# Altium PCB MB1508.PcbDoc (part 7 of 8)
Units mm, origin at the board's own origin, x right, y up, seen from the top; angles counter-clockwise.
Board outline 129 x 77 mm, 4 copper layers (Top Layer, GND, POWER, Bottom Layer), stack 1.582 mm thick; 399 components, 297 nets, 1407 pads, 1316 vias.
Unrouted connection lines stored in the file: 535.
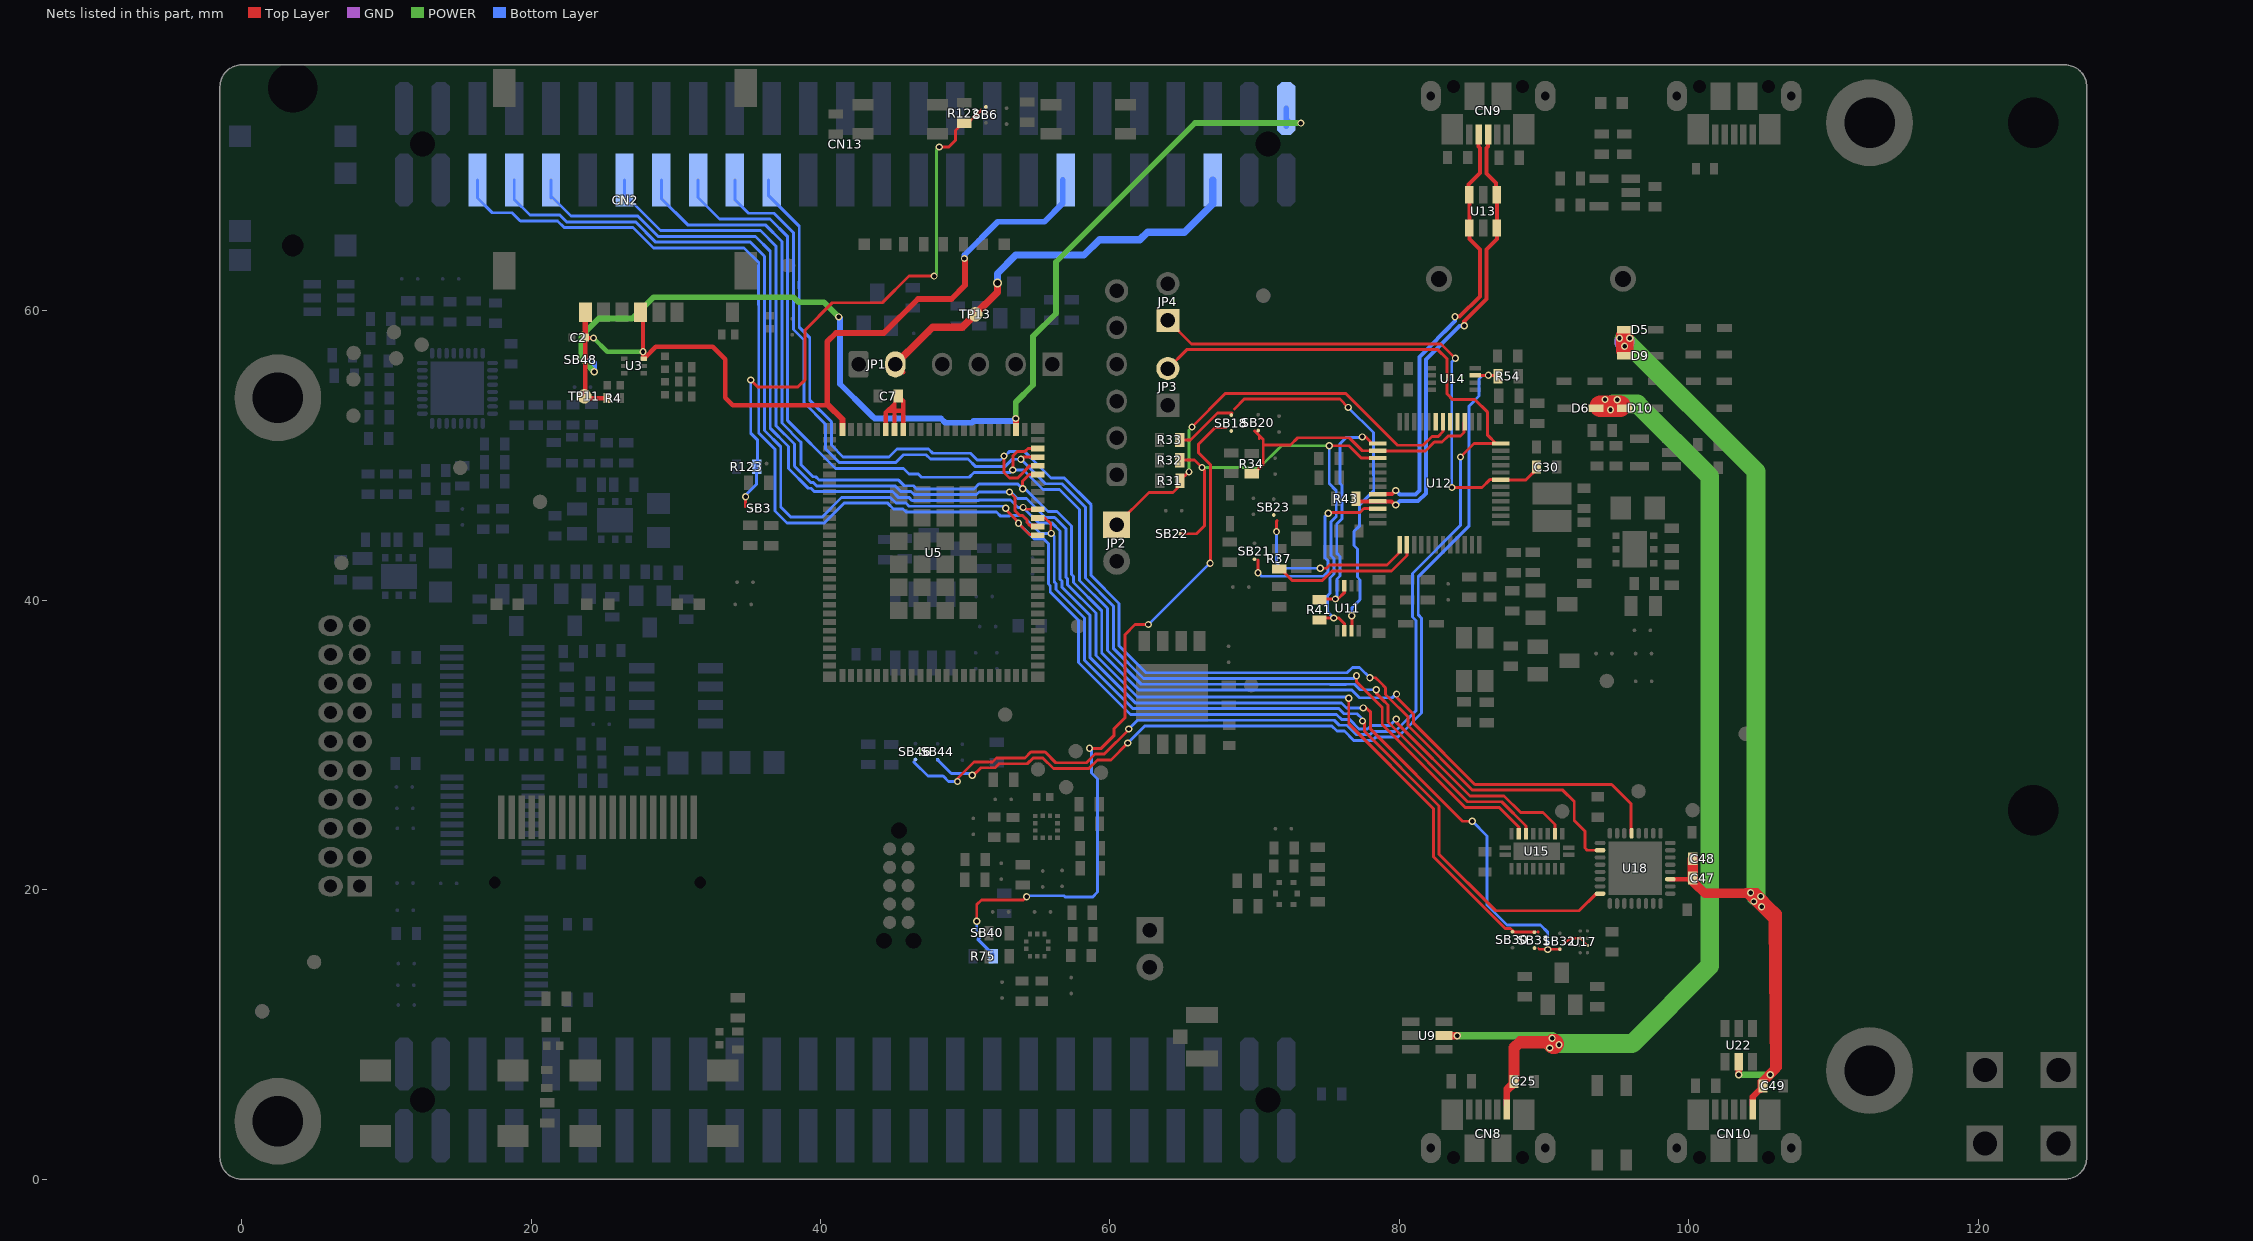
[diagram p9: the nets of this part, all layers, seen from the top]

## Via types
v1: diameter 0.5, hole 0.3, Top Layer to Bottom Layer, tented both sides, 1301 vias
v2: diameter 0.65, hole 0.4, Top Layer to Bottom Layer, tented both sides, 14 vias
v3: diameter 0.5/0.5/0.5/0.5 (per signal layer), hole 0.3, Top Layer to Bottom Layer, tented both sides, 1 vias

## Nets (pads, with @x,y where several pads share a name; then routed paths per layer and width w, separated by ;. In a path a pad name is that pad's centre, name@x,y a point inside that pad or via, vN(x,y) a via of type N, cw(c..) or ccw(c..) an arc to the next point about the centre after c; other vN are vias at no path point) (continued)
RFT_UART1_CTS: CN13.33 U5.26 U15.17 | length 93.1
  Top Layer w0.2: v1(53.29,49.011) 53.29,49.967 53.621,50.298 54.144,50.298 54.34,50.494 U5.26@55.013,50.494 ; v1(78.406,33.819) 78.406,33.572 78.854,33.124 79.218,32.76 79.218,31.582 84.719,26.081 87.073,26.081 88.756,24.398 U15.17@88.756,23.858
  Bottom Layer w0.2: CN13.33@31.54,69.045 31.54,67.84 33.031,66.349 36.508,66.349 37.731,65.125 37.731,62.35 37.728,62.347 37.728,61.229 37.731,61.226 37.731,52.413 41.031,49.113 45.73,49.113 46.124,48.719 46.759,48.719 46.975,48.503 50.275,48.503 50.608,48.837 53.116,48.837 v1(53.29,49.011) 54.02,49.011 55.375,47.656 56.515,47.656 57.904,46.267 57.904,41.379 59.835,39.447 59.835,36.524 62.161,34.198 75.204,34.198 75.206,34.197 76.324,34.197 76.325,34.198 76.902,34.198 77.281,33.819 v1(78.406,33.819)
RFT_UART1_RTS: CN13.35 U5.23 U18.29 | length 102.7
  Top Layer w0.2: v1(53.97,47.703) 53.97,48.237 54.426,48.694 U5.23@55.013,48.694 ; v1@79.823,33.579 79.823,33.287 80.99,32.12 80.99,31.507 85.216,27.281 94.674,27.281 95.997,25.958 95.997,23.954 U18.29@96.047,23.904
  Bottom Layer w0.2: CN13.35@29,69.045 29,67.774 30.825,65.949 36.187,65.949 37.331,64.805 37.331,62.516 37.328,62.513 37.328,61.063 37.331,61.06 37.331,52.245 38.661,50.915 ; 38.642,50.937 38.661,50.918 38.661,50.915 ; v1@79.823,33.579 79.513,33.269 77.245,33.269 76.716,33.798 76.491,33.798 76.49,33.797 75.04,33.797 75.039,33.798 61.996,33.798 59.435,36.358 59.435,39.282 57.479,41.238 57.479,41.657 57.352,41.784 57.352,45.126 56.347,46.131 55.723,46.131 54.151,47.703 v1(53.97,47.703) 53.636,48.037 50.939,48.037 50.606,47.703 46.643,47.703 46.428,47.919 45.793,47.919 45.444,48.267 45.398,48.313 39.895,48.313 39.667,48.541 39.49,48.541 38.661,49.37 38.661,50.915
  other v1: 79.812,33.519
RFT_UART1_RX: CN13.31 U5.25 U15.18 | length 88.8
  Top Layer w0.2: v1@53.981,49.894 U5.25@55.013,49.894 ; v1(77.043,34.789) 77.043,34.37 77.898,33.515 78.454,32.959 78.818,32.595 78.818,31.416 84.553,25.681 86.908,25.681 88.256,24.332 U15.18@88.256,23.858
  Bottom Layer w0.2: CN13.31@34.08,69.045 34.08,67.692 35.023,66.749 36.788,66.749 38.131,65.406 38.131,62.184 38.128,62.181 38.128,61.394 38.131,61.391 38.131,58.706 38.855,57.981 38.855,53.667 40.353,52.169 40.353,50.476 41.315,49.513 45.186,49.513 45.735,50.062 47.298,50.062 47.594,49.766 50.198,49.766 50.727,49.237 52.738,49.237 53.249,49.748 v1(53.849,49.748) ; v1@53.974,49.623 55.541,48.056 56.681,48.056 58.304,46.433 58.304,41.544 60.235,39.613 60.235,36.69 62.327,34.598 75.37,34.598 75.371,34.597 76.158,34.597 76.16,34.598 76.848,34.598 77.039,34.789 v1(77.043,34.789)
RFT_UART1_TX: CN13.29 U5.24 U18.2 | length 96.8
  Top Layer w0.2: v1(52.68,49.976) 52.68,48.843 53.062,48.461 53.628,48.461 54.461,49.294 U5.24@55.013,49.294 ; v1@52.74,49.951 52.74,49.963 v1@52.81,50.033 ; v1(77.964,34.65) 78.36,34.65 78.655,34.355 78.655,34.349 79.05,33.954 79.05,33.494 79.254,33.29 80.59,31.954 80.59,31.341 85.051,26.881 91.298,26.881 92.086,26.093 92.086,24.779 92.821,24.044 92.821,22.894 92.986,22.729 U18.2@93.872,22.729
  Bottom Layer w0.2: CN13.29@36.42,69.045 36.42,67.96 38.531,65.849 38.531,62.018 38.528,62.016 38.528,61.56 38.531,61.557 38.531,58.871 39.255,58.147 39.255,53.832 40.753,52.335 40.753,50.725 41.565,49.913 44.728,49.913 45.278,50.462 47.464,50.462 47.76,50.166 50.364,50.166 50.832,49.697 52.441,49.697 52.68,49.937 v1(52.68,49.976) ; v1@52.694,50.033 52.81,50.033 53.075,50.298 54.086,50.298 55.109,49.275 55.928,48.456 56.846,48.456 58.704,46.598 58.704,41.71 60.635,39.779 60.635,36.855 62.493,34.998 75.536,34.998 75.537,34.997 75.993,34.997 75.994,34.998 76.39,34.998 76.756,35.364 77.25,35.364 v1(77.964,34.65)
RFT_UART2_CTS: CN13.43 U5.16 U15.13 | length 108.1
  Top Layer w0.2: v1@52.884,46.369 52.884,46.194 v1@53.642,45.436 ; v1(53.685,45.32) 54.453,44.552 54.955,44.552 U5.16@55.013,44.494 ; v1(79.786,31.792) 79.786,31.579 84.885,26.481 87.239,26.481 88.384,25.335 89.919,25.335 90.756,24.498 U15.13@90.756,23.858
  Bottom Layer w0.2: CN13.43@18.84,69.045 18.84,67.703 19.917,66.626 21.981,66.626 22.452,66.155 27.211,66.155 28.617,64.749 35.155,64.749 36.131,63.772 36.131,63.013 36.128,63.01 36.128,60.566 36.131,60.563 36.131,51.73 37.255,50.607 37.255,46.457 37.966,45.746 40.095,45.746 41.461,47.113 44.814,47.113 45.208,46.719 45.901,46.719 46.116,46.503 52.621,46.503 v1@52.622,46.502 ; v1(53.685,45.32) 54.781,44.224 55.436,44.224 55.752,43.907 55.752,41.121 55.879,40.994 55.879,40.575 57.835,38.619 57.835,35.696 61.413,32.118 68.033,32.118 68.038,32.113 75.667,32.113 76.015,31.765 76.572,31.765 77.222,31.115 77.804,31.115 78.033,31.344 79.338,31.344 v1(79.786,31.792)
  other v1: 52.805,46.366
RFT_UART2_RTS: CN13.45 U5.18 U18.8 | length 118.3
  Top Layer w0.2: U5.18@55.013,45.694 55.516,45.694 55.911,45.299 55.911,44.658 v1(55.945,44.624) ; v1(77.45,31.665) 77.577,31.665 77.583,31.659 77.583,30.954 82.749,25.788 82.749,22.456 86.66,18.546 92.424,18.546 93.607,19.729 U18.8@93.872,19.729 U18.8@93.86,19.717
  Bottom Layer w0.2: CN13.45@16.3,69.045 16.3,67.794 17.312,66.782 18.679,66.782 19.256,66.205 21.836,66.205 ; 21.815,66.226 21.836,66.205 ; v1(77.45,31.665) 77.45,31.792 77.077,32.165 76.18,32.165 75.833,32.513 68.204,32.513 68.198,32.518 61.579,32.518 58.235,35.861 58.235,38.784 56.279,40.741 56.279,41.16 56.152,41.286 56.152,44.417 v1(55.945,44.624) 55.208,44.624 53.962,45.87 53.773,45.87 53.087,45.87 53.033,45.816 52.45,45.816 52.163,46.103 46.335,46.103 46.333,46.102 45.952,46.102 45.951,46.103 45.923,46.103 45.708,46.319 45.042,46.319 44.648,46.713 41.627,46.713 40.26,45.346 37.685,45.346 36.855,46.177 36.855,50.441 35.731,51.565 35.731,60.397 35.728,60.4 35.728,63.175 35.731,63.178 35.731,63.337 34.719,64.349 28.452,64.349 27.045,65.755 22.286,65.755 21.836,66.205
RFT_UART2_RX: CN13.41 SB31.1 SB32.2 U5.19 U17.B1 U17.C2 | length 112.4
  Top Layer w0.127: 89.596,15.972 89.68,15.888 ; U17.B1@92.499,16.65 U17.C2@92.999,16.15
  Top Layer w0.2: v1(54.001,46.42) 54.128,46.294 U5.19@55.013,46.294 ; v1(77.504,32.565) 77.716,32.565 78.018,32.263 78.018,31.085 84.372,24.731 v1(85.044,24.731) ; 89.68,15.888 SB32.2@91.094,15.888 ; 91.423,16.277 91.796,16.65 U17.B1@92.499,16.65
  Bottom Layer w0.2: CN13.41@21.38,67.793 CN13.41@21.38,67.942 ; CN13.41@21.38,69.045 CN13.41@21.38,67.942 ; v1(77.504,32.565) 76.346,32.565 75.999,32.913 68.369,32.913 68.364,32.918 61.745,32.918 58.635,36.027 58.635,38.95 56.679,40.907 56.679,41.326 56.552,41.452 56.552,44.794 56.016,45.331 55.091,45.331 v1(54.001,46.42) 53.646,46.42 53.13,46.937 50.971,46.937 50.937,46.903 46.312,46.903 46.096,47.119 45.374,47.119 44.979,47.513 39.564,47.513 39.336,47.741 39.158,47.741 37.795,49.105 37.795,50.632 36.531,51.896 36.531,60.729 36.528,60.731 36.528,62.844 36.531,62.847 36.531,64.12 35.502,65.149 28.783,65.149 27.377,66.555 22.767,66.555 CN13.41@21.38,67.942 ; v1(85.044,24.731) 85.058,24.731 86.065,23.724 86.065,18.952 87.447,17.57 89.753,17.57 90.256,17.067 v1(90.256,15.87)
RFT_UART2_TX: CN13.37 SB30.2 SB31.2 U5.17 | length 104.5
  Top Layer w0.2: v1(53.061,47.487) 53.451,47.097 53.451,46.192 53.773,45.87 53.962,45.87 54.263,45.569 54.263,45.369 54.439,45.194 ; v1(76.501,33.235) 76.501,31.47 82.349,25.622 82.349,22.291 86.901,17.739 86.908,17.739 87.315,17.332 87.686,17.332 87.946,17.072 SB31.2@89.342,17.072 ; 89.567,17.1 89.596,17.072 ; 54.439,45.194 54.913,45.194 U5.17@55.013,45.094 54.539,45.094 54.439,45.194
  Bottom Layer w0.2: CN13.37@26.46,69.045 26.46,68.037 28.949,65.549 35.851,65.549 36.931,64.468 36.931,62.681 36.928,62.678 36.928,60.897 36.931,60.894 36.931,52.062 38.195,50.798 38.195,49.27 39.324,48.141 39.501,48.141 39.73,47.913 45.145,47.913 45.539,47.519 46.262,47.519 46.478,47.303 50.772,47.303 50.955,47.487 v1(53.061,47.487) 53.161,47.487 53.606,47.042 54.243,47.042 55.554,45.731 56.182,45.731 56.952,44.96 56.952,41.618 57.079,41.491 57.079,41.073 59.035,39.116 59.035,36.193 61.91,33.318 76.501,33.318 v1(76.501,33.235)
SF_EN: R122.1 R123.1 SB3.2 SB6.2 | length 40.8
  Top Layer w0.2: 34.825,46.466 v1(34.825,47.165) ; v1@35.147,55.227 v1(35.181,55.227) 35.655,54.753 38.447,54.753 38.942,55.248 38.942,58.687 40.815,60.56 44.268,60.56 46.112,62.404 v1(47.851,62.404) ; v1(48.202,71.331) 48.863,71.331 49.326,71.794 49.326,72.461 49.841,72.975 R122.1@49.945,72.975 50.202,72.975 51.103,73.877
  POWER w0.2: v1(47.851,62.404) 48.003,62.556 48.003,71.132 v1(48.202,71.331)
  Bottom Layer w0.2: v1(34.825,47.165) 34.825,47.257 35.588,48.019 R123.1@35.588,49.224 35.633,49.269 35.633,51.097 35.181,51.549 35.181,55.194 v1@35.147,55.227
STL_USB_D_N: CN9.2 U12.32 U13.1 U13.6 | length 31.3
  Top Layer w0.279: U12.32@78.519,47.338 79.483,47.338 v1@79.758,47.612 ; v1(83.848,59.604) 84.161,59.604 85.56,61.003 85.56,64.25 84.838,64.972 U13.1@84.838,65.724 U13.6@84.838,68.024 ; U13.6@84.778,68.069 84.778,68.74 85.576,69.539 85.576,71.264 85.48,71.36 CN9.2@85.48,72.19
  Bottom Layer w0.279: v1(79.758,47.588) 80.029,47.316 81.113,47.316 81.383,47.586 81.383,56.826 83.848,59.291 ; 83.151,58.594 83.848,59.291 ; v1(83.848,59.604) 83.848,59.291
STL_USB_D_P: CN9.3 R43.1 U12.33 U13.3 U13.4 | length 32.5
  Top Layer w0.279: R43.1@77.037,46.888 77.088,46.838 U12.33@78.519,46.838 79.465,46.838 v1@79.758,46.545 ; v1(84.484,58.967) 84.484,59.28 86.017,60.813 86.017,64.25 86.738,64.972 U13.3@86.738,65.724 U13.4@86.738,68.024 ; CN9.3@86.13,72.19 86.13,71.36 86.034,71.264 86.034,69.494 86.678,68.85 U13.4@86.678,68.069
  Bottom Layer w0.279: v1(79.758,46.588) 80.029,46.859 81.303,46.859 81.841,47.397 81.841,56.637 83.475,58.271 84.171,58.967 v1(84.484,58.967)
STLK_RX: R54.1 SB44.1 U14.7 | length 64.1
  Top Layer w0.2: v1@50.527,27.873 51.085,28.43 52.052,28.43 52.327,28.704 54.291,28.704 54.699,29.113 55.362,29.113 56.095,28.379 58.542,28.379 59.135,28.973 60.066,28.973 v1(61.229,30.136) ; U14.7@85.251,55.546 v1(86.155,55.546) R54.1@86.611,55.546
  Bottom Layer w0.2: SB44.1@48.092,28.984 49.041,28.034 50.366,28.034 v1(50.485,27.915) ; v1(61.229,30.136) 62.396,31.303 74.871,31.303 74.88,31.313 75.336,31.313 75.683,30.965 76.202,30.965 76.852,30.315 78.136,30.315 78.364,30.544 79.871,30.544 80.17,30.842 80.18,30.842 81.541,32.204 81.541,38.767 81.305,39.004 81.305,41.627 84.826,45.148 84.826,51.193 84.808,51.211 84.808,53.412 85.505,54.109 85.505,55.301 85.75,55.546 v1(86.155,55.546)
STLK_TX: JP3.2 SB46.1 U12.12 | length 89.2
  Top Layer w0.2: v1@49.363,27.59 50.603,28.83 51.887,28.83 52.161,29.104 54.125,29.104 54.533,29.513 55.528,29.513 56.261,28.779 58.376,28.779 58.97,29.373 59.615,29.373 v1@61.321,31.079 ; JP3.2@64.004,56.018 65.307,57.321 82.654,57.321 83.304,56.671 83.304,54.257 83.694,53.867 85.23,53.867 86.105,52.992 86.105,51.404 U12.12@86.671,50.838 ; v1(84.225,49.901) 85.162,50.838 U12.12@86.671,50.838 ; U12.12@87.019,50.838 U12.12@86.671,50.838
  Bottom Layer w0.2: 46.443,28.815 46.472,28.815 47.432,27.855 48.478,27.855 48.849,27.484 v1(49.469,27.484) ; v1(61.296,31.104) 61.905,31.713 75.502,31.713 75.849,31.365 76.406,31.365 77.056,30.715 77.97,30.715 78.199,30.944 79.706,30.944 80.004,31.242 80.014,31.242 81.141,32.369 81.141,38.602 80.905,38.838 80.905,41.862 84.225,45.182 v1(84.225,49.901)
STM_JTCK: SB23.2 U12.37 | length 12.6
  Top Layer w0.2: v1(71.511,44.748) 71.511,45.468 71.559,45.517 ; v1(74.533,42.215) 74.958,42.215 75.181,42.437 79.155,42.437 80.019,43.301 U12.37@80.019,43.838
  Bottom Layer w0.2: v1(71.511,44.748) 71.511,42.57 71.866,42.215 v1(74.533,42.215)
STM_JTMS: SB21.2 U12.34 | length 13.7
  Top Layer w0.2: v1(70.237,41.907) 70.237,42.793 ; v1(75.092,46.025) 75.145,46.077 77.286,46.077 77.546,46.338 U12.34@78.519,46.338
  Bottom Layer w0.2: v1(70.237,41.907) 70.479,41.665 74.761,41.665 75.083,41.987 75.083,42.719 74.875,42.927 74.875,45.808 v1(75.092,46.025)
STM_RST: C30.1 JP4.1 U12.7 | length 36.5
  Top Layer w0.2: JP4.1@64.004,59.348 65.631,57.721 82.874,57.721 v1@83.844,56.751 ; v1@83.708,47.799 85.714,47.799 86.252,48.338 U12.7@87.019,48.338 87.05,48.306 88.742,48.306 89.599,49.163 C30.1@89.599,49.186 ; v1@83.844,56.689 v1@83.844,56.751 ; v1(83.875,56.721) v1@83.844,56.751
  Bottom Layer w0.2: v1(83.641,47.799) 83.622,47.818 83.622,56.467 v1@83.844,56.689
SWO: R75.2 SB18.2 SB40.1 | length 51.1
  Top Layer w0.2: v1(50.797,17.829) 50.797,18.98 51.118,19.302 54.022,19.302 v1(54.242,19.522) v1@54.255,19.535 ; v1(58.592,29.773) 59.407,29.773 60.27,30.636 60.27,31.11 61.055,31.894 61.055,37.647 61.734,38.326 v1(62.66,38.326) v1@62.677,38.343 ; v1@66.958,42.421 66.958,49.365 66.133,50.19 66.133,50.805 67.251,51.923 68.024,51.923
  Bottom Layer w0.2: 50.797,17.185 v1(50.797,17.829) ; 51.072,16.774 50.871,16.574 51.933,15.513 R75.2@51.933,15.414 ; v1@54.255,19.535 54.308,19.588 56.812,19.588 56.895,19.505 58.81,19.505 59.15,19.845 59.15,27.663 58.737,28.076 58.737,29.63 58.594,29.773 v1(58.592,29.773) ; v1(62.66,38.326) v1@66.981,42.647
  other v1: 66.922,42.555
T_JRST: U12.19
T_JTCK: R34.2 SB20.1 U12.15 U12.26 | length 19.5
  Top Layer w0.2: R34.2@69.936,48.743 70.593,49.399 70.593,50.73 ; 69.987,51.714 70.317,51.384 ; 70.317,51.181 70.317,51.384 ; U12.15@84.519,52.338 84.469,52.288 84.469,51.6 84.225,51.356 83.378,51.356 82.953,50.931 82.418,50.931 81.807,50.32 78.537,50.32 U12.26@78.519,50.338 77.431,50.338 76.533,51.235 72.977,51.235 72.472,50.73 70.593,50.73 ; 70.317,51.384 70.593,51.108 70.593,50.73
T_JTDI: U12.17
T_JTDO: U12.16
T_JTMS: R32.2 R41.2 SB22.1 U11.6 U12.27 | length 35.8
  Top Layer w0.2: R32.2@64.826,49.691 65.848,49.691 v1(66.365,49.174) 66.525,49.014 66.525,45.136 65.99,44.601 SB22.1@64.849,44.601 ; R41.2@74.483,38.633 74.629,38.78 v1(75.462,38.78) 75.813,38.78 76.207,38.385 76.207,38.163 U11.6@76.199,38.155 ; v1(75.155,50.685) 76.518,50.685 77.365,49.838 U12.27@78.519,49.838
  POWER w0.2: v1(66.365,49.174) 70.346,49.174 71.858,50.685 v1(75.155,50.685)
  Bottom Layer w0.2: v1(75.155,50.685) 75.155,48.064 75.642,47.577 75.642,45.797 75.275,45.43 75.275,43.093 75.492,42.876 75.492,42.286 75.483,42.277 75.483,41.821 75.208,41.546 75.208,40.492 75.031,40.315 75.031,39.211 v1(75.462,38.78)
T_NRST: JP2.1 R31.2 U12.18 | length 30.8
  Top Layer w0.2: JP2.1@60.464,45.229 62.693,47.458 64.359,47.458 64.843,47.941 R31.2@64.843,48.271 65.456,48.885 65.464,48.877 v1(65.468,48.877) ; v1(65.668,51.977) 67.997,54.305 76.286,54.305 79.871,50.72 81.641,50.72 82.252,51.331 82.687,51.331 83.019,51.663 U12.18@83.019,52.338
  POWER w0.2: v1(65.468,48.877) 65.468,51.777 v1(65.668,51.977)
T_SWDIO_IN: R41.1 U11.3 U12.25 | length 16
  Top Layer w0.2: R41.1@74.793,40.087 v1(75.581,40.087) 75.759,40.087 76.199,40.527 U11.3@76.199,41.001 ; U11.3@76.149,41.001 76.149,41.255 U11.3@76.199,41.255 ; v1(77.441,51.295) 77.676,51.295 U12.25@78.013,50.957 ; U12.25@78.492,50.838 U12.25@78.519,50.838
  Bottom Layer w0.2: v1(75.581,40.087) 75.702,40.208 75.702,41.474 75.899,41.671 75.899,43.035 75.675,43.259 75.675,45.264 76.042,45.631 76.042,47.936 75.892,48.085 75.892,50.82 76.334,51.262 77.409,51.262 v1(77.441,51.295)
T_SWO: R33.2 SB18.1 U11.7 | length 29.7
  Top Layer w0.2: R33.2@64.822,51.079 65.569,51.079 67.44,52.95 68.442,52.95 ; 68.599,53.221 69.284,53.905 75.891,53.905 v1(76.463,53.334) ; U11.7@76.699,38.155 76.692,38.161 76.718,38.187 v1(76.718,38.938)
  Bottom Layer w0.2: v1(76.463,53.334) 78.209,51.587 78.209,48.646 78.234,48.621 78.234,47.578 77.259,46.603 77.259,45.151 76.875,44.767 76.875,43.779 77.099,43.556 77.099,41.604 77.289,41.413 77.289,40.046 76.718,39.474 v1(76.718,38.938)
UartUsbVbus: C47.1 C48.2 C49.2 CN10.1 D5.1 D9.1 U18.19 U22.5 | length 108
  Top Layer w0.3: U18.19@98.722,20.729 100.157,20.729 C47.1@100.186,20.729 ; C47.1@100.59,20.5 101.142,19.949 v1@104.15,19.949
  Top Layer w0.45: v1(103.455,7.211) U22.5@103.455,8.115 ; v1@104.121,19.872 104.139,19.854 105.708,18.285 105.712,17.926 ; CN10.1@104.43,5.16 104.43,5.7 C49.2@104.907,6.177 ; C49.2@104.98,6.177 104.98,6.767 105.826,7.613 ; C49.2@105.186,6.652 106.03,7.496 106.03,7.613 105.835,7.613 ; 105.53,18.108 105.712,17.926 ; 105.721,17.926 105.721,17.917 ; 105.81,17.829 105.721,17.917 ; 105.937,18.665 106.216,18.386 106.216,7.693 106.064,7.54 ; 106,7.874 106,18.567 ; 106.043,7.831 105.835,7.622 ; 105.712,17.926 105.721,17.917 ; 105.721,17.917 105.835,7.622 ; 105.826,7.613 105.835,7.613 ; 105.826,7.613 105.835,7.622 ; 105.835,7.613 105.835,7.622
  Top Layer w0.5: C48.2@100.157,22.163 100.157,20.729 100.157,20.593 C47.1@100.374,20.376 ; C48.2@100.376,22.152 100.374,22.15 C47.1@100.374,20.376 ; 103.943,19.854 104.139,19.854 104.714,19.854 106,18.567 ; 105.555,18.12 104.008,19.667 101.084,19.667 C47.1@100.374,20.376
  Top Layer w1.2: 95.567,57.265 v1(95.567,57.556) 95.567,58.324
  GND w0.8: v1@95.867,57.88 ccw(c95.567,57.88) v1@95.867,57.88
  POWER w0.45: v1(103.455,7.211) v1(105.628,7.211)
  POWER w1.3: 95.517,58.039 104.654,48.902 104.654,46.237 104.654,19.796 104.654,19.517
  Bottom Layer w0.8: v1@95.867,57.88 ccw(c95.567,57.88) v1@95.867,57.88
  other v1: 105.035,18.818 104.502,19.186 104.98,19.542 104.273,19.796 95.217,58.106 95.917,58.106
USB_RENUMn: R37.2 U12.38 | length 10.6
  Top Layer w0.2: R37.2@71.663,42.158 71.804,42.158 72.582,41.381 74.69,41.381 75.346,42.037 79.454,42.037 80.519,43.102 U12.38@80.519,43.838
VBUS: C25.2 CN8.1 D6.1 D10.1 U9.5 | length 83.3
  Top Layer w0.4: 90.18,9.262 ccw(c90.673,9.346) 91.173,9.346 ccw(c90.673,9.346) 90.291,9.669 ccw(c90.673,9.346) 90.18,9.262
  Top Layer w0.45: CN8.1@87.43,5.16 87.43,6.26 C25.2@87.93,6.76 88.073,6.903 88.073,8.989 88.346,9.262 90.18,9.262 v1@91.039,9.262 ; 87.455,6.074 C25.2@87.955,6.574 ; C25.2@87.756,6.621 87.756,9.129 88.295,9.669 90.291,9.669 90.912,9.669
  Top Layer w0.5: U9.5@83.085,9.915 v1(84.002,9.915)
  Top Layer w1.5: D6.1@93.881,53.418 D10.1@95.251,53.418
  POWER w0.5: v1(84.002,9.915) 90.044,9.915 ; 89.635,9.808 90.18,9.262 ; 90.59,9.369 90.044,9.915 ; v1@90.795,9.747 90.627,9.915 90.044,9.915
  POWER w1.3: 90.59,9.369 96.087,9.369 101.452,14.735 101.452,48.562 96.456,53.558 94.761,53.558
  other v1: 90.387,9.059 91.039,9.288 90.556,9.745 94.593,53.177 94.212,53.873 95.057,53.867
VDD_MD: C7.2 CN13.5 JP1.2 TP13.1 U5.43 U5.44 U5.45 | length 37
  Top Layer w0.3: U5.45@44.513,51.794 44.513,52.976 45.113,53.576 45.113,53.09 ; 44.71,53.09 45.113,53.09 ; U5.44@45.113,51.991 45.113,53.09 ; JP1.2@45.174,56.308 JP1.2@45.713,55.769 ; C7.2@45.377,54.11 45.713,53.774 U5.43@45.713,51.794 ; 45.558,53.09 45.113,53.09
  Top Layer w0.5: JP1.2@45.174,56.308 47.023,58.158 47.032,58.158 47.738,58.863 49.802,58.863 TP13.1@50.7,59.762 52.232,61.293 v2(52.232,61.926)
  Bottom Layer w0.5: JP1.2@45.174,56.308 JP1.2@45.174,56.725 ; v2(52.232,61.926) 52.232,62.59 53.497,63.856 58.21,63.856 59.274,64.92 62.069,64.92 62.59,65.441 65.158,65.441 67.1,67.384 CN13.5@67.1,69.045
VDD_SIM: C2.1 CN2.C1 CN2.C6 CN13.13 R4.2 TP11.1 U3.6 U5.50 | length 60.6
  Top Layer w0.3: C2.1@23.731,58.151 C2.1@23.745,58.137 ; v1(24.316,58.13) 23.752,58.13 C2.1@23.745,58.137 ; R4.2@25.257,53.976 23.802,53.976 23.745,54.032 C2.1@23.745,58.137 ; CN2.C6@27.555,59.895 27.739,59.711 27.731,59.702 v1(27.731,57.184) 27.731,56.761 U3.6@27.798,56.694 28.622,57.518 32.558,57.518 33.42,56.656 33.42,53.999 33.935,53.483 38.997,53.483 ; 39.032,53.483 40.537,53.483
  Top Layer w0.4: C2.1@23.745,58.137 CN2.C1@23.745,59.645 ; U5.50@41.513,51.922 41.513,52.507 40.537,53.483 40.473,53.547 40.473,57.883 41.068,58.477 44.378,58.477 46.73,60.83 49.047,60.83 49.983,61.766 49.983,63.583 v1(49.942,63.624)
  POWER w0.3: v1(24.316,58.13) 25.263,57.184 v1(27.731,57.184)
  Bottom Layer w0.4: v1(49.942,63.624) 49.942,63.868 52.241,66.167 55.473,66.167 56.74,67.434 CN13.13@56.74,69.045
VDDIO_MDM: CN13.2 SB48.1 U5.30 | length 77.7
  Top Layer w0.4: v1(53.493,52.562) 53.513,52.543 U5.30@53.513,51.794
  POWER w0.4: v1(24.359,55.8) 23.486,56.673 23.486,58.278 24.678,59.47 26.979,59.47 28.458,60.95 38.139,60.95 38.495,60.594 40.247,60.594 v1(41.256,59.585) ; v1(53.493,52.562) 53.493,53.683 54.692,54.882 54.692,58.242 56.27,59.82 56.27,63.376 65.873,72.979 v1(73.196,72.979)
  Bottom Layer w0.4: v1(24.359,55.8) 24.359,56.418 ; v1(41.256,59.585) 41.355,59.485 41.355,54.954 43.273,53.037 43.654,52.655 43.747,52.562 48.333,52.562 48.626,52.27 50.457,52.27 50.574,52.387 50.985,52.387 ; 50.994,52.387 51.864,52.387 ; 51.873,52.387 v1@53.327,52.387 ; v1@53.327,52.396 v1(53.493,52.562) ; CN13.2@72.18,72.762 CN13.2@72.18,73.233 ; v1(73.196,72.979) 72.434,72.979 CN13.2@72.18,73.233 ; CN13.2@72.18,73.233 CN13.2@72.18,73.995 CN13.2@72.18,73.233
pads on no net: CN3.7 CN3.8 CN3.9 CN3.11 CN3.12 CN3.13 CN6.1 CN8.0 CN9.0 CN10.0 CN11.0 CN11.2 CN11.3 CN11.4 CN12.0 CN13.0 CN14.0 Designator7.1 Designator7.2 Designator14.1 Designator14.2 Designator15.1 Designator15.2 U1.H1 U12.4 U12.11 U12.14 U12.21 U12.22 U12.40 U12.41 U12.42 U12.43 U12.45 U12.46 U14.3 U15.4 U15.5 U15.8 U15.9 U15.11 U15.12 U15.15 U15.16 U18.9 U18.10 U18.11 U18.12 U18.13 U18.18 U18.21 U18.22 U18.25 U18.26 U18.31 U18.32 U19.3 U24.24 U24.25 U25.1 U25.3 U26.4 U27.9 U27.12 U28.9 U28.12 U29.7 U29.8 U29.9 U29.12 U29.13 U29.14 U30.1 U30.3
copper on no net: | length 66
  Top Layer w0.127: 110.48,39.469 111.75,39.469 ; 110.48,40.739 111.75,40.739 ; 110.48,42.009 111.75,42.009 ; 111.75,38.199 110.48,38.199 110.48,43.279 111.75,43.279 111.75,38.207
  GND w0.127: 110.48,39.469 111.75,39.469 ; 110.48,40.739 111.75,40.739 ; 110.48,42.009 111.75,42.009 ; 111.75,38.199 110.48,38.199 110.48,43.279 111.75,43.279 111.75,38.207
  POWER w0.127: 110.48,39.469 111.75,39.469 ; 110.48,40.739 111.75,40.739 ; 110.48,42.009 111.75,42.009 ; 111.75,38.199 110.48,38.199 110.48,43.279 111.75,43.279 111.75,38.207
  Bottom Layer w0.127: 110.48,39.469 111.75,39.469 ; 110.48,40.739 111.75,40.739 ; 110.48,42.009 111.75,42.009 ; 111.75,38.199 110.48,38.199 110.48,43.279 111.75,43.279 111.75,38.207
  other v1: 18.664,14.186 5.657,43.078 6.32,44.285 7.539,44.818 8.651,45.311

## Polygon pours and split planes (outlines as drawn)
GND on POWER "Top Layer-GND" (solid, remove dead copper, pour order 44): -1.5,77 127.5,77 127.5,0 -1.5,0
3V3_STLK on POWER "POWER-3V3_STLK" (solid, remove dead copper, pour order 8): 76.075,42.676 76.075,43.378 76.797,44.099 78.525,44.099 78.877,44.451 78.877,44.948 78.525,45.299 77.979,45.299 77.638,45.641 77.638,47.005 78.222,47.589 78.222,48.086 77.425,48.882 77.425,50.296 76.266,51.455 76.266,52.134 78.469,54.337 79.218,54.337 79.867,53.688 79.867,49.639 78.877,48.649 78.877,46.286 80.44,44.723 83.766,44.723 84.241,45.198 84.241,49.068 86.404,51.231 90.364,51.231 91.299,50.296 93.053,50.296 93.282,50.067 93.282,49.049 93.089,48.856 89.449,48.856 88.842,49.463 88.205,49.463 87.858,49.115 87.858,48.38 86.853,47.375 86.853,43.755 87.141,43.466 87.141,40.772 86.698,40.329 85.712,40.329 85.283,39.899 85.283,39.038 85.221,38.976 83.308,38.976 82.394,39.89 80.352,39.89 79.63,40.613 79.141,40.613 78.248,41.505 77.246,41.505
1V8 on POWER "POWER-1V8" (solid, remove dead copper, pour order 2): 85.049,14.543 85.049,23.943 86.687,25.582 92.52,25.582 94.192,27.329 94.192,35.611 95.063,36.382 97.634,36.382 98.722,35.295 98.722,20.004 99.495,19.231 99.495,16.281 94.47,11.256 88.336,11.256
GND on Bottom Layer "Top Layer-GND" (solid, remove dead copper, pour order 46): -1.5,77 127.5,77 127.5,0 -1.5,0
no net on Bottom Layer "Bottom Layer-No Net" (solid, pour order 38): 114.264,7.672
GND on Top Layer "Top Layer-GND" (solid, remove dead copper, pour order 40): -1.5,77 127.5,77 127.5,0 -1.5,0
GND on GND "Top Layer-GND" (solid, remove dead copper, pour order 42): -1.5,77 127.5,77 127.5,0 -1.5,0

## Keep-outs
Keep-Out Layer:
  lines w0.127: -1.5,4.999 -1.5,71.999
  lines w0.2: -1.5,1.5 ccw(c0,1.5) 0,0 126,0 ccw(c126,1.5) 127.5,1.5 127.5,75.5 ccw(c126,75.5) 126,77 0,77 ccw(c0,75.5) -1.5,75.5 -1.5,1.5
  lines w1: 65.196,18.066 65.196,15.066 69.451,15.066 ; 65.196,22.492 65.196,25.992 69.451,25.992 ; 73.269,15.066 77.805,15.066 ; 73.805,25.992 77.805,25.992 77.805,15.142

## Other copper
Top Layer:
  rectangle net VDD_MD: 44.982,53.132 45.9,55.919
  rectangle net GND: 49.383,21.793 50.653,22.602
  rectangle net GND: 54.243,26.184 55.208,27.042
  region net GND: 11.142,71.083 11.142,70.984 13.753,68.372 13.753,68.428 14.039,68.715 14.039,68.74
  region net GND: 11.379,70.846 11.936,70.288 12.023,70.382 11.475,70.93
  region net GND: 13.753,69.599 13.753,68.364 17.016,65.101 17.042,65.127 17.206,65.127 17.206,65.151
  region net 5V: 10.662,73.171 10.836,72.997 10.836,70.915 10.63,70.709 10.647,70.693
  pour cut-out: 47.863,65.408 50.365,65.408 50.404,65.37 49.591,64.558 49.591,63.979 49.298,63.979 49.127,63.808 48.835,64.1 48.431,64.1
  region net GND: 99.661,19.667 100.033,19.295 100.044,19.295 100.069,19.269 100.462,19.269 100.462,19.325 100.058,19.729
  region net GND: 87.382,20.758 87.382,21.24 87.258,21.363 87.015,21.363 87.015,21.227 86.756,20.968 87.005,20.718 87.005,20.523
  region net GND: 86.74,21.447 86.389,21.798 85.947,21.798 85.893,21.852 85.893,21.26 86.08,21.073 86.465,21.073 86.465,20.632 86.66,20.438 86.711,20.489 86.771,20.489
  region net GND: 28.637,33.689 28.657,33.689 30.831,33.689 30.831,32.979 28.637,32.979
  pour cut-out: 65.196,25.992 77.805,25.992 77.805,15.066 65.196,15.066
  pour cut-out: 73.857,40.936 73.857,38.838 73.76,38.741 74.355,38.146 77.275,38.146 77.275,40.726 76.699,41.302
  region: 110.297,6.555
  pour cut-out: 83.346,51.888 83.347,51.888 85.103,51.888 85.103,52.35 84.374,53.08 84.374,53.361 83.847,53.361 83.822,53.386
  pour cut-out: 67.437,33.75 67.437,32.376 68.462,32.376 69.091,33.005 69.091,33.722
  region net GND: 47.515,48.959
  region net GND: 47.515,48.959
  region net GND: 47.515,48.959 47.019,47.885 49.349,47.852 48.657,48.959
  region: 101.723,49.617
  region net VDD_SIM: 27.715,57.108 28.112,57.108 28.112,57.069 27.796,56.753 27.739,56.753
  region net NC_SIM_IO: 30.703,53.402 31.109,53.808 31.109,53.832 31.208,53.832 31.26,53.78 31.26,53.402
  region net 5V_USB_CHG: 102.103,53.9 103.386,53.9 103.386,53.688 103.423,53.651 102.933,53.161 102.879,53.161 102.763,53.277 102.647,53.161 102.128,53.161 102.128,53.226 102.077,53.277
  region net 5V_USB_CHG: 84.104,69.35 84.137,69.383 84.137,69.997 84.73,70.59 84.977,70.343 84.977,69.521 84.722,69.266
  region net 5V: 97.025,47.055 96.701,47.379 96.701,47.742 96.825,47.838 97.006,47.838 98.459,47.838 98.579,47.665 98.579,47.387 98.222,47.03 98.098,47.03
  region net 5V: 97.116,45.897 97.057,45.658 97.395,44.755 97.749,44.755 97.823,44.829 97.573,45.079 97.573,45.519
  region net 1V8: 94.187,35.918 94.187,35.39 94.367,35.209 96.587,35.209 96.797,35.419 96.797,35.954
  region net 1V8_CS: 82.657,31.15 82.431,31.376 82.352,31.376 82.352,31.894 82.276,31.97 82.336,32.03 82.5,32.03 82.5,31.872 82.877,31.496 82.885,31.496
  pour cut-out: 34.713,38.91 34.76,38.862 35.194,38.862 35.359,39.027 35.274,39.027 35.147,39.154 35.112,39.119 34.684,39.119 34.592,39.027
  region net GND: 44.243,61.678 44.502,61.937 44.502,62.037 44.422,62.037 44.16,61.775 44.16,61.759 44.141,61.759 44.049,61.667 44.047,61.667
  region net GND: 67.394,35.257 66.666,35.985 66.418,35.958 66.229,35.726 66.197,35.358 67.078,34.76
  pour cut-out: 28.53,33.999 28.637,33.891 28.637,32.736 27.428,32.736 27.169,32.996 24.133,32.996 23.605,33.524 23.658,33.577 23.658,34.043
  pour cut-out: 30.831,34.034 30.831,32.754 30.849,32.736 31.037,32.924 35.532,32.924 35.998,33.39 35.935,33.452 35.935,33.981 35.881,33.981 35.828,34.034
  region net GND: 85.259,20.523 85.103,20.679 85.153,20.729 85.153,21.02 85.23,21.097 85.802,21.097 85.802,20.904 86.056,20.65 85.929,20.523 85.929,20.472
  region net GND: 100.935,20.887 100.935,20.727 101.29,20.372 101.326,20.407 102.256,20.407 102.256,20.928 102.425,21.097 102.257,21.264 102.257,21.439 101.935,21.439 101.109,22.265
  pour cut-out: 91.058,11.062 95.072,11.062 95.492,11.481 95.462,11.511 95.462,12.176 95.272,12.176 94.402,13.046 91.345,13.046 89.611,14.419 89.068,13.358 90.422,12.203
  pour cut-out: 33.478,13.149 33.478,10.745 33.863,11.129 35.3,11.129 35.3,11.505 35.572,11.776 35.534,11.814 35.534,12.451 35.322,12.451 35.292,12.48
  region net GND: 77.743,38.419 77.674,38.488 77.499,38.488 77.362,38.626 77.362,39.809 78.252,40.7 79.369,40.7 79.546,40.292 79.507,40.026 79.507,38.488
  pour cut-out: 79.748,40.843 79.775,40.816 79.775,40.317 80.562,40.317 80.613,40.368 82.543,40.368 82.543,40.553 82.721,40.731 82.479,40.973 81.185,40.973 81.045,41.113 80.848,40.916 79.822,40.916
  region net GND: 91.345,48.515 91.276,48.446 90.21,48.446 90.21,49.436 90.31,49.536 90.31,50.618 90.658,50.618 90.757,50.717
  pour cut-out: 88.835,54.245 88.847,54.257 90.594,54.257 90.594,54.017 90.818,53.794 90.798,53.774 90.798,52.828 90.713,52.828 90.484,52.6 90.448,52.636 88.843,52.636 88.843,52.68 88.835,52.687
  pour cut-out: 87.166,57.616 87.204,57.578 87.83,57.578 87.83,57.168 87.674,57.012 87.674,56.707 87.44,56.707 87.421,56.689 87.398,56.712 87.175,56.712
  region net GND: 93.124,43.299 93.579,43.754 93.542,43.792 93.542,43.968 93.245,43.968 93.223,43.99 93.106,43.873 92.839,43.873 92.712,43.746 92.745,43.713 92.745,43.383 92.763,43.365
  region net GND: 96.925,45.137 96.925,44.624 96.118,44.624 96.095,44.601 95.947,44.748 95.453,44.748 95.453,45.093 95.497,45.137
  region net GND: 95.446,42.298 95.446,41.912 95.492,41.867 95.65,42.025 97.012,42.025 97.012,42.299 96.771,42.54 96.853,42.621 96.853,42.761
  pour cut-out: 105.219,5.704 106.357,5.704 106.403,5.75 106.318,5.835 106.318,6.671 106.369,6.721 106.199,6.891 105.447,6.891
  region net GND: 106.555,7.275 106.284,7.004 106.284,6.806 106.377,6.806 106.673,6.51 106.8,6.428 107.537,6.583 107.537,7.018 107.334,7.221 107.334,7.399
  pour cut-out: 85.6,7.56 86.029,7.56 86.029,7.335 85.903,7.208 85.903,6.403 85.883,6.383 85.64,6.625 85.391,6.625 85.391,6.88 85.294,6.977
  pour cut-out: 86.983,9.452 87.039,9.508 87.377,9.508 87.756,9.129 87.385,8.758 87.385,6.668 87.445,6.609 87.346,6.51 86.829,6.51
  region net 1V8: 33.672,45.073 33.392,45.073 32.833,45.632 32.833,46.013 33.011,46.191
  pour cut-out: 22.14,69.52 22.177,69.482 25.824,69.482 25.824,67.432 26.077,67.18 25.359,66.462 25.359,65.346 24.052,65.346 23.77,65.063 23.487,65.346 21.988,65.346 21.988,65.432 22.064,65.509 22.064,65.571
  region net GND: -1.041,55.312 -1.041,51.114 -0.898,50.971 -0.898,49.963 -0.237,49.963 -0.237,56.701
  region net GND: 96.406,47.324 96.399,47.761 95.947,47.761 95.858,47.85 95.453,47.445 94.492,47.988 93.956,47.354 95.444,46.689 95.444,46.653 95.834,46.264 96.366,46.264
  pour cut-out: 63.313,52.255 65.203,52.255 64.499,51.551 64.499,47.668 64.521,47.647 63.451,47.647 63.451,47.932 63.313,48.069
  region net GND: 86.893,36.108 88.469,36.108 88.612,35.965 88.612,34.61 88.538,34.535 88.489,34.584 86.957,34.584 86.906,34.634
  region net GND: 86.893,36.225 86.893,37.891 85.959,38.825 85.642,38.825 85.642,38.363 85.516,38.237 85.69,38.063 85.69,36.276 85.596,36.182
  region net GND: 96.417,41.924 96.943,41.924 96.957,41.911 96.885,41.839 96.885,39.13 96.682,38.927 96.429,38.927
  region net GND: 101.565,54.967 101.768,54.726 101.794,54.493 101.646,54.345 101.559,54.345
  pour cut-out: 102.861,62.905 103.013,62.752 104.181,62.752 104.181,62.168 103.929,61.915 103.929,57.977 103.724,57.977 103.013,57.266 102.731,57.548 101.611,57.548 101.611,58.3 101.796,58.485
  region net GND: 91.789,67.37 91.789,67.373 91.03,68.132 90.929,68.031 90.399,68.031 90.262,67.894 90.262,66.461 90.923,65.8 90.999,65.876 91.668,65.876
  region net GND: 96.644,67.881 98.357,67.881 98.423,67.815 98.441,67.833 98.441,68.399 98.492,68.609 98.111,68.609 98.019,68.518 96.687,68.518 96.357,68.188
  pour cut-out: 93.183,71.892 93.164,71.872 93.164,71.358 94.263,71.358 94.481,71.14 94.552,71.21 96.366,71.21 96.366,71.791 96.039,72.118 96.039,72.152 95.614,72.152 95.544,72.223
  region net GND: 93.931,61.732 96.826,61.732 96.084,60.99 94.673,60.99
  pour cut-out: 99.635,41.83 99.634,41.828 99.634,41.51 99.492,41.51 99.436,41.453 98.564,41.453 98.228,41.789 98.33,41.89 98.33,42.018 98.408,42.018 98.459,42.068 98.479,42.048 99.304,42.048
  region net GND: 3.178,14.295 4.957,16.074 5.14,16.074 6.064,15.151 6.064,14.394 6.748,13.709
  region net GND: 104.43,71.678 104.453,71.7 106.692,71.7 106.692,71.229 106.711,71.21 106.318,70.817 106.318,70.459 104.262,70.459 104.181,70.539
  region net GND: 106.711,73.62 106.699,73.608 106.114,73.608 106.114,71.515 106.064,71.464 106.533,70.994 107.051,70.994 107.051,71.036 107.305,71.29
  region net GND: 84.295,73.448 84.521,73.222 87.43,73.222 87.43,73.905 87.496,73.971 87.099,74.368 85.317,74.368 85.265,74.419
  region net GND: 101.295,73.448 101.521,73.222 104.43,73.222 104.43,73.905 104.496,73.971 104.099,74.368 102.317,74.368 102.265,74.419
  region net GND: 87.965,3.552 87.739,3.778 84.83,3.778 84.83,3.095 84.764,3.029 85.161,2.632 86.943,2.632 86.995,2.581
  region net GND: 104.965,3.552 104.739,3.778 101.83,3.778 101.83,3.095 101.764,3.029 102.161,2.632 103.943,2.632 103.995,2.581
  region net GND: 115.5,9.075 115.5,3.959 115.319,3.959 114.419,4.859 114.546,4.987 114.546,11.093
  region net GND: 115.5,74.575 115.5,69.459 115.319,69.459 114.419,70.359 114.546,70.487 114.546,76.492
  text "1" at 110.674,42.787 h0.89 r270
GND:
  region net GND: 94.251,54.566 94.252,54.566 94.837,54.566 94.91,54.493 94.857,54.44 94.235,54.44 94.16,54.515 93.943,54.515
  region net GND: 45.49,17.063 45.458,17.031 45.153,17.031 45.006,17.178 45.006,17.439 45.151,17.583
  region net 3V3_STLK: 92.968,50.238 93.114,50.092 93.114,49.074 92.996,48.956 91.899,48.956 91.794,49.061 91.794,50.121 91.911,50.238
  region net VBUS: 94.058,54.134 95.182,54.134 95.328,53.988 95.328,53.704 95.155,53.53 94.936,53.53 94.896,53.49 94.896,53.026 94.753,52.882 94.438,52.882 94.326,52.995 94.326,53.514 94.244,53.597 94.045,53.597 93.931,53.711 93.931,54.007 94.058,54.134
  region net 5V: 91.953,54.835 92.099,54.689 92.099,53.672 91.98,53.553 90.884,53.553 90.779,53.658 90.779,54.718 90.895,54.835
  region net EXT_BAT: 95.176,56.093 95.311,55.958 95.311,55.681 94.785,55.155 94.785,55.002 94.632,54.849 94.369,54.849 94.197,55.02 94.197,55.438 94.101,55.535 93.503,55.535 93.375,55.663 93.375,55.968 93.5,56.093
  region net GND: 15.088,71.82 15.092,71.737 15.106,71.7 15.213,71.799 15.213,71.941 15.157,71.941 15.088,71.872
  region net GND: 15.212,71.8
  region net GND: 115.5,9.075 115.5,3.959 115.319,3.959 114.419,4.859 114.546,4.987 114.546,11.093
  region net GND: 115.5,74.575 115.5,69.459 115.319,69.459 114.419,70.359 114.546,70.487 114.546,76.492
  text "2" at 110.674,41.705 h0.89 r270
POWER:
  region net GND: 45.49,17.063 45.458,17.031 45.153,17.031 45.006,17.178 45.006,17.439 45.151,17.583
  region net GND: 45.448,17.052
  region net GND: 51.479,41.365 51.578,41.266 52.989,41.266 53.116,41.393 52.98,41.53 52.98,41.596
  region net GND: 49.07,38.2 49.122,38.147 55.36,38.147 55.412,38.2 55.331,38.281 55.331,38.462
  region net 3V3: 22.318,46.48 22.173,46.335 22.016,46.491 21.991,46.491 21.991,46.563 22.021,46.593
  region: -10.813,43.677
  region net GND: 44.463,24.875 44.635,25.047 44.815,25.047 44.289,24.522
  region net GND: 44.469,35.029 44.355,35.143 44.165,35.143 44.15,35.127 44.564,34.713 44.794,34.713
  pour cut-out: 56.978,14.49 57.37,14.882 57.37,27.053 54.226,30.196 50.685,30.196 50.685,29.303 51.986,28.002 51.986,14.821 51.655,14.49
  region net UartUsbVbus: 105.301,19.672 105.301,18.665 105.154,18.518 104.722,18.518 104.118,19.151 104.095,19.39
  region: 92.003,34.108
  region net 1V8_MD: 92.032,34.124 92.032,34.311 92.276,34.555 92.962,34.555 93.337,34.179 93.337,33.539 92.999,33.201 92.383,33.201
  region net 3V3: 21.472,45.918 21.141,46.249 21.141,46.624 21.319,46.802 22.234,46.802 22.361,46.675 22.361,46.243 21.953,45.835
  region net 5V: 91.202,53.336 90.773,53.766 90.773,54.632 90.976,54.835 91.894,54.835 92.217,54.479 92.217,54.378
  region net VBUS: 94.761,52.905 94.456,52.905 93.948,53.413 93.948,54.048 94.106,54.205 94.735,54.205
  region net 1V8_MD: 43.136,42.322 42.741,42.322 42.392,42.671 42.392,43.038 42.793,43.439 42.973,43.439
  region net 1V8: 41.79,43.821 41.917,43.948 41.917,45.368 41.709,45.576 41.208,45.576 41.054,45.421 41.054,43.907
  region net 1V8: 40.8,43.789 40.8,44.125 41.079,44.404 41.179,44.304 41.231,44.304 41.231,43.987 41.151,43.907 41.054,43.907
  region net 1V8: 32.875,46.107 32.749,45.982 32.749,45.546 32.885,45.411 33.434,45.411 33.434,45.828
  region net 1V8: 32.951,45.142 33.553,45.142 33.688,45.276 33.688,45.62 33.48,45.828 33.434,45.828
  pour cut-out: 67.18,24.808 75.208,24.808 75.208,17.751 67.18,17.751
  region: 42.089,42.368
  region net 5V: 96.363,48.226
  region net 5V: 97.457,46.262
  region net 5V: 96.582,48.03 96.582,47.543 97.794,46.33 97.963,46.33 97.963,46.603 98.214,46.854 97.863,47.205 97.863,47.797 97.475,48.185
  region net GND: 89.967,51.69
  region net GND: 89.967,51.69 90.691,51.573 90.703,51.665 90.647,51.736 89.946,51.826
  pour cut-out: 48.203,37.259
  pour cut-out: 47.527,37.948 46.029,36.45 47.063,36.45 48.172,35.341 61.472,35.341 61.472,35.881 60.635,36.37 59.006,37.193 55.546,37.193
  pour cut-out: 23.124,18.64 23.132,18.649 24.486,18.649 24.486,30.734 30.329,36.577 30.201,36.577 29.476,37.302 28.035,35.862 27.556,35.862 27.556,35.385 23.124,30.953
  pour cut-out: 18.977,41.799 18.995,41.781 21.191,41.781 21.191,43.16 21.445,43.414 21.427,43.432 21.427,46.491 20.196,46.491 20.141,46.546 20.161,46.546
  pour cut-out: 16.458,57.556 16.817,57.556 18.397,55.976 18.04,55.618 17.238,54.497 17.081,52.346 16.898,52.53 15.794,52.53 15.794,52.574 15.73,52.638
  region net GND: 101.614,53.476 101.452,53.638 101.452,53.466 101.448,53.462 101.533,53.378 101.618,53.378 101.693,53.303
  region net GND: 115.5,9.075 115.5,3.959 115.319,3.959 114.419,4.859 114.546,4.987 114.546,11.093
  region net GND: 115.5,74.575 115.5,69.459 115.319,69.459 114.419,70.359 114.546,70.487 114.546,76.492
  text "3" at 110.649,40.399 h0.89 r270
